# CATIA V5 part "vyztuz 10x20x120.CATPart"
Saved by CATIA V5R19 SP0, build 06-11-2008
Part number: Part46
Bounding box of the stored display mesh (mm): x -60 to 60, y -5 to 5, z 0 to 20
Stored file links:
  C:\Users\jsmid\Desktop\DP_Smidak_Forma LEGO\vyztuz 10x20x120.CATPart
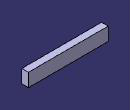
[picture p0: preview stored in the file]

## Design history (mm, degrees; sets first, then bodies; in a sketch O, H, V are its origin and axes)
Body1 (main body)
  Sketch1 on xy-plane, origin (0, 0, 0), H (1, 0, 0), V (0, 1, 0)
    line L1 (60, 5) -> (60, -5)
    line L2 (60, -5) -> (-60, -5)
    line L3 (-60, -5) -> (-60, 5)
    line L4 (-60, 5) -> (60, 5)
    length L4 = 120
    length L1 = 10
    vertical: L1 V, L3 V
    horizontal: L2 H, L4 H
    equidistance: L1 L3 O, L2 L4 O
  Pad1: profile Sketch1, direction (0, 0, 1), length 20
